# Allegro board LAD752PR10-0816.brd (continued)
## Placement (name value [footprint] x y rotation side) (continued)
PC813  22U_0603_6.3V6M  [C_0603]  228.42 38.39 90 bottom
PC814  1U_0603_6.3V6M  [C_0603]  236.99 36.42 90 bottom
PC815  22U_0603_6.3V6M  [C_0603]  198.25 80.97 0 bottom
PC816  22U_0603_6.3V6M  [C_0603]  196.99 86.24 180 bottom
PC818  330P_0402_50V7K  [C_0402]  122.01 123.41 180 bottom
PC819  22P_0603_50V8  [C_0603]  235.47 41.69 270 bottom
PC820  22U_0603_6.3V6M  [C_0603]  227.34 35.19 180 bottom
PC1000  220U_D7_2VM_R6M  [C_EEFSS0D221R]  165.21 126.27 0 bottom
PC1001  220U 2.5V Y D2 ESR9M H1.9 SX  [C_D2]  170.89 125.35 0 top
PC1002  220U 2.5V Y D2 ESR9M H1.9 SX  [C_D2]  161.7 125.51 180 top
PC1003  47U_0603_6.3V6M  [C_0603]  177.17 127.89 270 bottom
PC1004  47U_0603_6.3V6M  [C_0603]  175.52 127.89 270 bottom
PC1005  47U_0805_6.3V6M  [C_0805]  164.77 107.09 0 top
PC1006  47U_0603_6.3V6M  [C_0603]  178.82 127.89 270 bottom
PC1007  220U 2.5V Y D2 ESR9M H1.9 SX  [C_D2]  151.8 130.46 180 top
PC1008  220U_D7_2VM_R6M  [C_EEFSS0D221R]  151.16 126.27 180 bottom
PC1009  220U 2.5V Y D2 ESR9M H1.9 SX  [C_D2]  151.67 125.7 180 top
PC1010  220U_D7_2VM_R6M  [C_EEFSS0D221R]  155.3 126.27 0 bottom
PC1011  47U_0603_6.3V6M  [C_0603]  151.52 131.79 180 bottom
PC1012  47U_0603_6.3V6M  [C_0603]  145.36 130.59 180 bottom
PC1013  47U_0603_6.3V6M  [C_0603]  151.52 130.59 180 bottom
PC1014  47U_0603_6.3V6M  [C_0603]  145.36 129.32 180 bottom
PC1015  47U_0603_6.3V6M  [C_0603]  151.52 129.32 180 bottom
PC1016  47U_0603_6.3V6M  [C_0603]  145.36 131.86 180 bottom
PC1017  220U_D2_2.5VY_R9M  [C_D2]  180.83 125.38 0 top
PC1018  47U_0805_6.3V6M  [C_0805]  164.77 108.8 0 top
PC1019  10U_0402_6.3V6M  [C_0402]  165.55 113.06 0 top
PC1020  22U_0603_6.3V6M  [C_0603]  156.86 107.66 0 top
PC1021  22U_0603_6.3V6M  [C_0603]  156.86 106.46 0 top
PC1022  22U_0603_6.3V6M  [C_0603]  155.91 107.66 180 top
PC1023  22U_0603_6.3V6M  [C_0603]  155.91 106.46 180 top
PC1024  22U_0603_6.3V6M  [C_0603]  160.61 106.46 180 top
PC1025  22U_0603_6.3V6M  [C_0603]  160.61 107.66 180 top
PC1026  22U_0603_6.3V6M  [C_0603]  161.56 107.66 0 top
PC1027  22U_0603_6.3V6M  [C_0603]  161.56 106.46 0 top
PC1028  22U_0603_6.3V6M  [C_0603]  140.73 108.04 0 top
PC1029  22U_0603_6.3V6M  [C_0603]  138.38 108.04 0 top
PC1030  22U_0603_6.3V6M  [C_0603]  145.43 108.04 0 top
PC1031  22U_0603_6.3V6M  [C_0603]  143.08 108.04 0 top
PC1032  22U_0603_6.3V6M  [C_0603]  147.78 108.04 0 top
PC1033  22U_0603_6.3V6M  [C_0603]  150.51 108.11 0 top
PC1034  22U_0603_6.3V6M  [C_0603]  150.52 109.32 0 top
PC1035  22U_0603_6.3V6M  [C_0603]  150.52 110.66 0 top
PC1036  10U_0402_6.3V6M  [C_0402]  164.68 111.03 180 top
PC1037  10U_0402_6.3V6M  [C_0402]  165.55 112.17 0 top
PC1038  10U_0402_6.3V6M  [C_0402]  165.55 114.46 0 top
PC1039  10U_0402_6.3V6M  [C_0402]  164.68 111.92 180 top
PC1040  10U_0402_6.3V6M  [C_0402]  164.68 110.14 180 top
PC1041  10U_0402_6.3V6M  [C_0402]  165.55 110.14 0 top
PC1042  1U_0201_6.3V6M  [C_0201]  164.84 113.44 180 top
PC1043  1U_0201_6.3V6M  [C_0201]  164.84 114.58 180 top
PC1044  1U_0201_6.3V6M  [C_0201]  164.84 114.01 180 top
PC1045  10U_0402_6.3V6M  [C_0402]  155.48 111.03 180 top
PC1046  10U_0402_6.3V6M  [C_0402]  156.34 109.76 0 top
PC1047  10U_0402_6.3V6M  [C_0402]  155.48 111.92 180 top
PC1048  10U_0402_6.3V6M  [C_0402]  155.48 109.76 180 top
PC1049  10U_0402_6.3V6M  [C_0402]  156.34 111.92 0 top
PC1050  10U_0402_6.3V6M  [C_0402]  158.91 105.19 180 top
PC1051  10U_0402_6.3V6M  [C_0402]  156.34 111.03 0 top
PC1052  10U_0402_6.3V6M  [C_0402]  156.21 105.19 0 top
PC1053  10U_0402_6.3V6M  [C_0402]  158.91 104.3 180 top
PC1054  10U_0402_6.3V6M  [C_0402]  160.09 109.76 0 top
PC1055  10U_0402_6.3V6M  [C_0402]  156.21 104.3 0 top
PC1056  10U_0402_6.3V6M  [C_0402]  159.22 109.76 180 top
PC1057  10U_0402_6.3V6M  [C_0402]  159.22 111.92 180 top
PC1058  10U_0402_6.3V6M  [C_0402]  159.22 111.03 180 top
PC1059  10U_0402_6.3V6M  [C_0402]  153.08 112.72 180 top
PC1060  10U_0402_6.3V6M  [C_0402]  143.12 105.72 0 top
PC1061  10U_0402_6.3V6M  [C_0402]  138.56 104.8 0 top
PC1062  10U_0402_6.3V6M  [C_0402]  140.84 106.6 0 top
PC1063  10U_0402_6.3V6M  [C_0402]  140.85 111.39 0 top
PC1064  10U_0402_6.3V6M  [C_0402]  148.03 109.12 0 top
PC1065  10U_0402_6.3V6M  [C_0402]  145.56 109.11 0 top
PC1066  10U_0402_6.3V6M  [C_0402]  138.6 110.48 0 top
PC1067  10U_0402_6.3V6M  [C_0402]  143.14 111.39 0 top
PC1068  10U_0402_6.3V6M  [C_0402]  138.56 105.7 0 top
PC1069  10U_0402_6.3V6M  [C_0402]  143.12 104.81 0 top
PC1070  10U_0402_6.3V6M  [C_0402]  140.86 110.52 0 top
PC1071  10U_0402_6.3V6M  [C_0402]  160.09 111.92 0 top
PC1072  10U_0402_6.3V6M  [C_0402]  159.77 104.3 0 top
PC1073  10U_0402_6.3V6M  [C_0402]  160.09 111.03 0 top
PC1074  10U_0402_6.3V6M  [C_0402]  159.77 105.19 0 top
PC1075  10U_0402_6.3V6M  [C_0402]  162.78 111.92 180 top
PC1076  10U_0402_6.3V6M  [C_0402]  162.78 109.76 180 top
PC1077  10U_0402_6.3V6M  [C_0402]  162.46 104.3 180 top
PC1078  10U_0402_6.3V6M  [C_0402]  162.78 111.03 180 top
PC1079  10U_0402_6.3V6M  [C_0402]  163.33 104.3 0 top
PC1080  10U_0402_6.3V6M  [C_0402]  163.33 105.19 0 top
PC1081  10U_0402_6.3V6M  [C_0402]  166.02 105.19 180 top
PC1082  10U_0402_6.3V6M  [C_0402]  162.46 105.19 180 top
PC1083  10U_0402_6.3V6M  [C_0402]  155.35 105.19 180 top
PC1084  10U_0402_6.3V6M  [C_0402]  155.35 104.3 180 top
PC1085  10U_0402_6.3V6M  [C_0402]  147.78 104.79 0 top
PC1086  10U_0402_6.3V6M  [C_0402]  147.79 106.59 0 top
PC1087  10U_0402_6.3V6M  [C_0402]  145.45 104.79 0 top
PC1088  10U_0402_6.3V6M  [C_0402]  147.97 111.44 0 top
PC1089  10U_0402_6.3V6M  [C_0402]  145.44 106.59 0 top
PC1090  10U_0402_6.3V6M  [C_0402]  150.05 104.8 0 top
PC1091  10U_0402_6.3V6M  [C_0402]  153.05 111.85 180 top
PC1092  10U_0402_6.3V6M  [C_0402]  145.44 105.69 0 top
PC1093  10U_0402_6.3V6M  [C_0402]  150.06 105.68 0 top
PC1094  10U_0402_6.3V6M  [C_0402]  140.83 104.81 0 top
PC1095  10U_0402_6.3V6M  [C_0402]  145.49 111.4 0 top
PC1096  10U_0402_6.3V6M  [C_0402]  143.14 110.52 0 top
PC1097  1U_0201_6.3V6M  [C_0201]  163.12 101.12 180 top
PC1098  1U_0201_6.3V6M  [C_0201]  164.65 102.58 180 top
PC1099  1U_0201_6.3V6M  [C_0201]  158.66 101.7 0 top
PC1100  1U_0201_6.3V6M  [C_0201]  159.82 109 180 top
PC1101  1U_0201_6.3V6M  [C_0201]  165.27 102.58 0 top
PC1102  1U_0201_6.3V6M  [C_0201]  162.6 113.25 0 top
PC1103  1U_0201_6.3V6M  [C_0201]  162.6 112.68 0 top
PC1104  1U_0201_6.3V6M  [C_0201]  161.98 113.25 180 top
PC1105  1U_0201_6.3V6M  [C_0201]  162.23 109 180 top
PC1106  1U_0201_6.3V6M  [C_0201]  161.98 112.68 180 top
PC1107  1U_0201_6.3V6M  [C_0201]  161.98 114.27 180 top
PC1108  1U_0201_6.3V6M  [C_0201]  161.98 114.84 180 top
PC1109  1U_0201_6.3V6M  [C_0201]  162.6 114.84 0 top
PC1110  1U_0201_6.3V6M  [C_0201]  162.6 114.27 0 top
PC1111  1U_0201_6.3V6M  [C_0201]  160.44 109 0 top
PC1112  10U_0402_6.3V6M  [C_0402]  145.51 110.52 0 top
PC1113  10U_0402_6.3V6M  [C_0402]  150.08 106.58 0 top
PC1114  10U_0402_6.3V6M  [C_0402]  138.56 106.6 0 top
PC1115  10U_0402_6.3V6M  [C_0402]  140.88 109.12 0 top
PC1116  10U_0402_6.3V6M  [C_0402]  140.84 105.7 0 top
PC1117  10U_0402_6.3V6M  [C_0402]  138.6 111.37 0 top
PC1118  10U_0402_6.3V6M  [C_0402]  138.58 109.13 0 top
PC1119  10U_0402_6.3V6M  [C_0402]  147.98 110.53 0 top
PC1120  10U_0402_6.3V6M  [C_0402]  143.12 106.62 0 top
PC1121  10U_0402_6.3V6M  [C_0402]  147.79 105.69 0 top
PC1122  10U_0402_6.3V6M  [C_0402]  143.12 109.11 0 top
PC1123  1U_0201_6.3V6M  [C_0201]  155.36 113.25 0 top
PC1124  1U_0201_6.3V6M  [C_0201]  157.15 112.68 180 top
PC1125  1U_0201_6.3V6M  [C_0201]  155.36 112.68 0 top
PC1126  1U_0201_6.3V6M  [C_0201]  154.74 113.25 180 top
PC1127  1U_0201_6.3V6M  [C_0201]  157.15 113.25 180 top
PC1128  1U_0201_6.3V6M  [C_0201]  157.15 114.84 180 top
PC1129  1U_0201_6.3V6M  [C_0201]  154.74 112.68 180 top
PC1130  1U_0201_6.3V6M  [C_0201]  157.15 114.27 180 top
PC1131  1U_0201_6.3V6M  [C_0201]  155.36 114.84 0 top
PC1132  1U_0201_6.3V6M  [C_0201]  155.36 114.27 0 top
PC1133  1U_0201_6.3V6M  [C_0201]  154.74 114.27 180 top
PC1134  1U_0201_6.3V6M  [C_0201]  163.74 101.12 0 top
PC1135  1U_0201_6.3V6M  [C_0201]  154.74 114.84 180 top
PC1136  1U_0201_6.3V6M  [C_0201]  162.86 109 0 top
PC1137  1U_0201_6.3V6M  [C_0201]  160.44 103.15 0 top
PC1138  1U_0201_6.3V6M  [C_0201]  152.57 113.9 180 top
PC1139  1U_0201_6.3V6M  [C_0201]  145.87 114.44 0 top
PC1140  1U_0201_6.3V6M  [C_0201]  144.03 103.5 180 top
PC1141  1U_0201_6.3V6M  [C_0201]  150.13 113.89 180 top
PC1142  1U_0201_6.3V6M  [C_0201]  150.18 112.26 180 top
PC1143  1U_0201_6.3V6M  [C_0201]  146.68 103.51 180 top
PC1144  1U_0201_6.3V6M  [C_0201]  149.09 102.94 180 top
PC1145  1U_0201_6.3V6M  [C_0201]  138.49 112.78 0 top
PC1146  1U_0201_6.3V6M  [C_0201]  149.09 103.51 180 top
PC1147  1U_0201_6.3V6M  [C_0201]  144.03 102.92 180 top
PC1148  1U_0201_6.3V6M  [C_0201]  149.71 102.94 0 top
PC1149  1U_0201_6.3V6M  [C_0201]  140.31 112.19 180 top
PC1150  1U_0201_6.3V6M  [C_0201]  150.18 112.85 180 top
PC1151  1U_0201_6.3V6M  [C_0201]  140.96 112.78 0 top
PC1152  1U_0201_6.3V6M  [C_0201]  148.38 112.26 0 top
PC1153  1U_0201_6.3V6M  [C_0201]  142.79 112.19 180 top
PC1154  1U_0201_6.3V6M  [C_0201]  148.38 112.84 0 top
PC1155  1U_0201_6.3V6M  [C_0201]  143.45 112.79 0 top
PC1156  1U_0201_6.3V6M  [C_0201]  149.71 103.51 0 top
PC1157  1U_0201_6.3V6M  [C_0201]  148.33 113.88 0 top
PC1158  1U_0201_6.3V6M  [C_0201]  150.81 112.28 0 top
PC1159  1U_0201_6.3V6M  [C_0201]  148.33 114.46 0 top
PC1160  1U_0201_6.3V6M  [C_0201]  152.57 114.47 180 top
PC1161  1U_0201_6.3V6M  [C_0201]  158.02 102.58 0 top
PC1162  1U_0201_6.3V6M  [C_0201]  162.8 101.76 180 top
PC1163  1U_0201_6.3V6M  [C_0201]  162.23 103.15 180 top
PC1164  1U_0201_6.3V6M  [C_0201]  162.86 103.15 0 top
PC1165  1U_0201_6.3V6M  [C_0201]  158.02 103.16 0 top
PC1166  1U_0201_6.3V6M  [C_0201]  158.03 109 0 top
PC1167  1U_0201_6.3V6M  [C_0201]  159.82 103.15 180 top
PC1168  1U_0201_6.3V6M  [C_0201]  159.57 112.68 180 top
PC1169  1U_0201_6.3V6M  [C_0201]  157.41 109 180 top
PC1170  1U_0201_6.3V6M  [C_0201]  160.19 113.25 0 top
PC1171  1U_0201_6.3V6M  [C_0201]  159.57 113.25 180 top
PC1172  1U_0201_6.3V6M  [C_0201]  160.19 112.68 0 top
PC1173  1U_0201_6.3V6M  [C_0201]  157.78 112.68 0 top
PC1174  1U_0201_6.3V6M  [C_0201]  157.78 113.25 0 top
PC1175  1U_0201_6.3V6M  [C_0201]  159.57 114.27 180 top
PC1176  1U_0201_6.3V6M  [C_0201]  144.88 103.51 0 top
PC1177  1U_0201_6.3V6M  [C_0201]  145.9 112.23 0 top
PC1178  1U_0201_6.3V6M  [C_0201]  144.88 102.94 0 top
PC1179  1U_0201_6.3V6M  [C_0201]  145.87 113.86 0 top
PC1180  1U_0201_6.3V6M  [C_0201]  142.77 113.84 180 top
PC1181  1U_0201_6.3V6M  [C_0201]  147.3 103.51 0 top
PC1182  1U_0201_6.3V6M  [C_0201]  146.68 102.94 180 top
PC1183  1U_0201_6.3V6M  [C_0201]  145.23 114.43 180 top
PC1184  1U_0201_6.3V6M  [C_0201]  145.27 112.8 180 top
PC1185  1U_0201_6.3V6M  [C_0201]  145.23 113.85 180 top
PC1186  1U_0201_6.3V6M  [C_0201]  139.82 102.92 0 top
PC1187  1U_0201_6.3V6M  [C_0201]  138.48 112.19 0 top
PC1188  1U_0201_6.3V6M  [C_0201]  140.31 112.77 180 top
PC1189  1U_0201_6.3V6M  [C_0201]  139.2 103.49 180 top
PC1190  1U_0201_6.3V6M  [C_0201]  140.3 114.42 180 top
PC1191  1U_0201_6.3V6M  [C_0201]  139.2 102.92 180 top
PC1192  1U_0201_6.3V6M  [C_0201]  140.3 113.84 180 top
PC1193  1U_0201_6.3V6M  [C_0201]  145.27 112.21 180 top
PC1194  1U_0201_6.3V6M  [C_0201]  150.13 114.47 180 top
PC1195  1U_0201_6.3V6M  [C_0201]  143.42 113.86 0 top
PC1196  1U_0201_6.3V6M  [C_0201]  140.96 112.19 0 top
PC1197  1U_0201_6.3V6M  [C_0201]  143.41 114.43 0 top
PC1198  1U_0201_6.3V6M  [C_0201]  147.3 102.94 0 top
PC1199  1U_0201_6.3V6M  [C_0201]  159.57 114.84 180 top
PC1200  1U_0201_6.3V6M  [C_0201]  157.78 114.27 0 top
PC1201  1U_0201_6.3V6M  [C_0201]  157.78 114.84 0 top
PC1202  1U_0201_6.3V6M  [C_0201]  160.19 114.27 0 top
PC1203  1U_0201_6.3V6M  [C_0201]  160.19 114.84 0 top
PC1204  1U_0201_6.3V6M  [C_0201]  165.27 103.15 0 top
PC1205  1U_0201_6.3V6M  [C_0201]  164.65 103.15 180 top
PC1206  1U_0201_6.3V6M  [C_0201]  154.99 102.58 180 top
PC1207  1U_0201_6.3V6M  [C_0201]  165.07 102.01 0 top
PC1208  1U_0201_6.3V6M  [C_0201]  154.99 103.15 180 top
PC1209  1U_0201_6.3V6M  [C_0201]  155.62 103.15 0 top
PC1210  1U_0201_6.3V6M  [C_0201]  155.44 101.76 180 top
PC1211  1U_0201_6.3V6M  [C_0201]  155.62 102.58 0 top
PC1212  1U_0201_6.3V6M  [C_0201]  157.41 102.58 180 top
PC1213  1U_0201_6.3V6M  [C_0201]  157.85 101.12 180 top
PC1214  1U_0201_6.3V6M  [C_0201]  145.9 112.81 0 top
PC1215  1U_0201_6.3V6M  [C_0201]  142.79 112.78 180 top
PC1216  1U_0201_6.3V6M  [C_0201]  150.81 112.87 0 top
PC1217  1U_0201_6.3V6M  [C_0201]  147.69 114.45 180 top
PC1218  1U_0201_6.3V6M  [C_0201]  150.77 113.89 0 top
PC1219  1U_0201_6.3V6M  [C_0201]  140.95 114.42 0 top
PC1220  1U_0201_6.3V6M  [C_0201]  151.5 102.94 180 top
PC1221  1U_0201_6.3V6M  [C_0201]  143.44 112.2 0 top
PC1222  1U_0201_6.3V6M  [C_0201]  142.77 114.42 180 top
PC1223  1U_0201_6.3V6M  [C_0201]  142.24 103.49 0 top
PC1224  1U_0201_6.3V6M  [C_0201]  140.95 113.83 0 top
PC1225  1U_0201_6.3V6M  [C_0201]  138.48 113.84 0 top
PC1226  1U_0201_6.3V6M  [C_0201]  138.47 114.43 0 top
PC1227  1U_0201_6.3V6M  [C_0201]  139.82 103.49 0 top
PC1228  1U_0201_6.3V6M  [C_0201]  150.77 114.46 0 top
PC1229  1U_0201_6.3V6M  [C_0201]  141.62 102.93 180 top
PC1230  1U_0201_6.3V6M  [C_0201]  147.74 112.25 180 top
PC1231  1U_0201_6.3V6M  [C_0201]  142.25 102.91 0 top
PC1232  1U_0201_6.3V6M  [C_0201]  147.69 113.86 180 top
PC1233  1U_0201_6.3V6M  [C_0201]  151.5 103.51 180 top
PC1234  1U_0201_6.3V6M  [C_0201]  147.74 112.83 180 top
PC1235  1U_0201_6.3V6M  [C_0201]  141.62 103.5 180 top
PC1236  1U_0201_6.3V6M  [C_0201]  155.62 109 0 top
PC1237  1U_0201_6.3V6M  [C_0201]  157.41 103.15 180 top
PC1238  1U_0201_6.3V6M  [C_0201]  154.99 109 180 top
PC1300  22U_0603_6.3V6M  [C_0603]  101.71 51.96 0 bottom
PC1301  0.1U_0402_16V7K  [C_0402]  100.12 50.71 90 bottom
PC1302  22U_0603_6.3V6M  [C_0603]  201.94 76.11 90 bottom
PC1303  22U_0603_6.3V6M  [C_0603]  100.91 38.51 180 bottom
PC1304  22U_0603_6.3V6M  [C_0603]  100.91 39.78 180 bottom
PC1305  22P_0603_50V8  [C_0603]  100.91 41.05 180 bottom
PC1306  22U_0603_6.3V6M  [C_0603]  101.71 50.75 0 bottom
PC1307  1U_0603_6.3V6M  [C_0603]  104.18 49.63 270 bottom
PC1308  22U_0603_6.3V6M  [C_0603]  200.73 76.11 90 bottom
PC1309  10U_0603_6.3V6M  [C_0603]  214.13 75.91 270 bottom
PC1310  22P_0603_50V8  [C_0603]  211.65 75.91 270 bottom
PC1311  0.01U_0402_16V7K  [C_0402]  202.02 72.23 180 top
PC1312  1U_0603_6.3V6M  [C_0603]  202.89 79.34 180 bottom
PC1313  10U_0603_6.3V6M  [C_0603]  212.86 75.91 270 bottom
PC1314  22U_0603_6.3V6M  [C_0603]  210.32 80.3 180 bottom
PC1315  22U_0603_6.3V6M  [C_0603]  210.32 79.04 180 bottom
PC5002  4.7U_0402_6.3V6M  [C_0402]  182.1 141.73 180 top
PC5003  1U_0603_6.3V6M  [C_0603]  124.21 113.76 0 bottom
PC5005  1U_0402_6.3V6K  [C_0402]  157.33 141.51 270 top
PC5006  1U_0402_6.3V6K  [C_0402]  165.88 139.99 0 top
PC5007  1U_0402_6.3V6K  [C_0402]  174.03 141.54 270 top
PC5008  1U_0402_6.3V6K  [C_0402]  141.33 144.79 270 top
PC5009  1U_0402_6.3V6K  [C_0402]  149.63 144.85 270 top
PC5010  1000P_0402_50V7K  [C_0402]  119.56 134.34 0 bottom
PC5011  1000P_0402_50V7K  [C_0402]  121.1 147.36 270 bottom
PC5013  1U_0402_25V6K  [C_0402]  163.2 142.77 0 top
PC5014  1000P_0402_50V7K  [C_0402]  163.2 141 0 top
PC5015  1U_0402_25V6K  [C_0402]  171.65 142.65 270 top
PC5016  1000P_0402_50V7K  [C_0402]  172.35 145.13 90 top
PC5017  1U_0402_25V6K  [C_0402]  184.98 145.83 270 top
PC5018  1000P_0402_50V7K  [C_0402]  184.1 145.83 270 top
PC5019  1U_0402_25V6K  [C_0402]  147.14 146.15 270 top
PC5020  1000P_0402_50V7K  [C_0402]  148.03 148.5 90 top
PC5021  1U_0402_25V6K  [C_0402]  157.16 148.8 180 top
PC5022  1000P_0402_50V7K  [C_0402]  155.65 146.09 270 top
PC5023  1U_0402_25V6K  [C_0402]  184.91 142.3 180 top
PC5024  1000P_0402_50V7K  [C_0402]  186.06 139.1 270 top
PC5025  1U_0402_25V6K  [C_0402]  118.7 118.84 180 bottom
PC5026  1000P_0402_50V7K  [C_0402]  118.7 119.79 180 bottom
PC5027  2.2U_0402_16V6K  [C_0402]  123.07 113.77 270 bottom
PC6000  4.7U_0603_6.3V  [C_0603]  287.79 55.47 180 top
PC6001  0.01U_0603_25V7K  [C_0603]  293.76 49.44 180 top
PC6002  0.1U_0603_16V  [C_0603]  286.43 57.59 0 top
PC6003  0.1U_0402_16V7K  [C_0402]  286.99 56.55 0 top
PC6004  0.01U_0402_16V  [C_0402]  283.42 57.5 180 top
PC6005  0.068U_0402_16V7K  [C_0402]  281.44 54.12 90 bottom
PC6006  0.068U_0402_16V7K  [C_0402]  280.55 59.77 90 bottom
PC6007  330P_0402_25V  [C_0402]  289.11 63.6 0 bottom
PC6008  2200P_0402_25V  [C_0402]  288.17 62.66 270 bottom
PC6009  47P_0402_50V8J  [C_0402]  289.96 61.75 180 bottom
PC6010  0.068U_0402_16V7K  [C_0402]  281.68 63.46 180 bottom
PC6011  1000P_0402_25V  [C_0402]  292.69 61.75 180 bottom
PC6012  2200P_0603_50V7K  [C_0603]  291.98 64.1 270 bottom
PC6013  2200P_0603_50V7K  [C_0603]  293.25 65.06 270 bottom
PC6014  1500P_0402_50V7K  [C_0402]  285.33 61.69 180 bottom
PC6015  390P_0402_50V7K  [C_0402]  285.33 62.64 180 bottom
PC6016  1000P_0402_25V  [C_0402]  286.58 59.52 90 top
PC6017  2200P_0402_25V  [C_0402]  287.16 65.39 270 bottom
PC6018  1000P_0402_25V  [C_0402]  283.98 59.96 90 top
PC6019  330P_0402_25V  [C_0402]  288.35 50.13 0 bottom
PC6020  2200P_0402_25V  [C_0402]  287.35 51.14 90 bottom
PC6021  47P_0402_50V8J  [C_0402]  290.13 51.02 0 bottom
PC6022  0.068U_0402_16V7K  [C_0402]  283.93 52.36 180 bottom
PC6023  1000P_0402_25V  [C_0402]  283.03 50.57 90 bottom
PC6024  1000P_0402_25V  [C_0402]  286.7 53.5 0 top
PC6025  1500P_0402_50V7K  [C_0402]  286.46 49.38 270 bottom
PC6026  390P_0402_50V7K  [C_0402]  287.35 49.38 270 bottom
PC6027  1000P_0402_25V  [C_0402]  284.91 54.46 270 top
PC6028  2200P_0402_25V  [C_0402]  286.46 51.23 270 bottom
PC6029  0.068U_0402_16V7K  [C_0402]  281.44 58.01 90 bottom
PC6107  1U_0402_25V6K  [C_0402]  250.83 51.49 270 bottom
PC6108  1000P_0402_50V7K  [C_0402]  254.25 52.32 90 top
PC6109  0.1U_0402_25V6  [C_0402]  252.48 52.34 90 top
PC6110  2200P_0402_50V7K  [C_0402]  253.36 52.34 90 top
PC6111  10U_0805_25V6K~D  [C_0805]  254.7 51.36 270 bottom
PC6112  10U_0805_25V6K~D  [C_0805]  254.73 51.34 270 top
PC6113  10U_0805_25V6K~D  [C_0805]  252.94 51.36 270 bottom
PC6114  10U_0805_25V6K~D  [C_0805]  253 51.34 270 top
PC6117  1U_0603_25V6K  [C_0603]  249.42 55.24 90 top
PC6118  2.2U_0603_10V6K  [C_0603]  247.91 54.12 0 top
PC6127  0.22U_0603_25V7K  [C_0603]  249.75 50.06 90 bottom
PC6128  2200P_0402_50V7K  [C_0402]  252.82 59.55 0 top
PC6129  100U_25V_M  [C_ECST250ADA101MF611]  266.26 38.73 270 bottom
PC6131  100U_25V_M  [C_ECST250ADA101MF611]  261.28 37.05 0 bottom
PC6205  1U_0603_25V6K  [C_0603]  240.9 55.2 90 top
PC6206  2.2U_0603_10V6K  [C_0603]  239.32 54.03 0 top
PC6207  1U_0402_25V6K  [C_0402]  242.3 51.53 270 bottom
PC6208  1000P_0402_50V7K  [C_0402]  242.41 51.51 270 top
PC6209  0.1U_0402_25V6  [C_0402]  240.56 51.51 270 top
PC6210  2200P_0402_50V7K  [C_0402]  241.47 51.51 270 top
PC6211  10U_0805_25V6K~D  [C_0805]  245.49 51.36 270 top
PC6212  10U_0805_25V6K~D  [C_0805]  245.42 51.43 270 bottom
PC6213  10U_0805_25V6K~D  [C_0805]  243.76 51.36 270 top
PC6214  10U_0805_25V6K~D  [C_0805]  243.66 51.43 270 bottom
PC6215  0.22U_0603_25V7K  [C_0603]  241.18 50.07 90 bottom
PC6216  2200P_0402_50V7K  [C_0402]  244.27 59.46 0 top
PC6217  1U_0603_25V6K  [C_0603]  232.3 55.2 90 top
PC6218  2.2U_0603_10V6K  [C_0603]  230.76 53.94 0 top
PC6219  1U_0402_25V6K  [C_0402]  233.73 51.53 270 bottom
PC6220  1000P_0402_50V7K  [C_0402]  233.83 51.51 270 top
PC6221  0.1U_0402_25V6  [C_0402]  231.99 51.51 270 top
PC6222  2200P_0402_50V7K  [C_0402]  232.9 51.51 270 top
PC6223  10U_0805_25V6K~D  [C_0805]  235.19 51.36 270 top
PC6224  10U_0805_25V6K~D  [C_0805]  236.91 51.36 270 top
PC6225  10U_0805_25V6K~D  [C_0805]  236.85 51.43 270 bottom
PC6226  10U_0805_25V6K~D  [C_0805]  235.09 51.43 270 bottom
PC6227  0.22U_0603_25V7K  [C_0603]  232.61 50.07 90 bottom
PC6228  2200P_0402_50V7K  [C_0402]  235.71 59.46 0 top
PC6305  1U_0603_25V6K  [C_0603]  223.62 56.22 90 top
PC6306  2.2U_0603_10V6K  [C_0603]  222.06 54.96 0 top
PC6307  1U_0402_25V6K  [C_0402]  225.04 52.53 270 bottom
PC6308  1000P_0402_50V7K  [C_0402]  225.14 52.51 270 top
PC6309  0.1U_0402_25V6  [C_0402]  223.29 52.51 270 top
PC6310  2200P_0402_50V7K  [C_0402]  224.21 52.51 270 top
PC6311  10U_0805_25V6K~D  [C_0805]  228.16 50.9 270 bottom
PC6312  10U_0805_25V6K~D  [C_0805]  226.39 50.9 270 bottom
PC6313  10U_0805_25V6K~D  [C_0805]  226.49 52.43 270 top
PC6314  10U_0805_25V6K~D  [C_0805]  228.22 52.43 270 top
PC6315  0.22U_0603_25V7K  [C_0603]  223.92 51.07 90 bottom
PC6316  2200P_0402_50V7K  [C_0402]  227.03 60.46 0 top
PC6400  1U_0603_25V6K  [C_0603]  263.15 57.82 90 top
PC6401  2.2U_0603_10V6K  [C_0603]  266.01 53.75 180 bottom
PC6402  1U_0402_25V6K  [C_0402]  276.55 50.39 270 bottom
PC6403  1000P_0402_50V7K  [C_0402]  277.44 50.39 270 bottom
PC6404  0.1U_0402_25V6  [C_0402]  277.44 51.33 90 bottom
PC6405  2200P_0402_50V7K  [C_0402]  275.68 50.39 270 bottom
PC6406  10U_0805_25V6K~D  [C_0805]  274.38 50.36 270 bottom
PC6407  10U_0805_25V6K~D  [C_0805]  275.97 51.56 90 bottom
PC6408  10U_0805_25V6K~D  [C_0805]  272.63 50.41 270 bottom
PC6409  10U_0805_25V6K~D  [C_0805]  270.86 50.41 270 bottom
PC6410  0.22U_0603_25V7K  [C_0603]  269.35 48.88 90 bottom
PC6411  2200P_0402_50V7K  [C_0402]  275.52 57.44 0 bottom
PC6501  22U_0805_6.3VAM  [C_0805]  268.84 68.29 90 bottom
PC6502  22U_0805_6.3VAM  [C_0805]  271.18 68.22 90 bottom
PC6503  22U_0805_6.3VAM  [C_0805]  273.64 68.22 90 bottom
PC6504  22U_0805_6.3VAM  [C_0805]  275.43 68.24 90 bottom
PC6505  22U_0603_6.3V6M  [C_0603]  255.7 79.09 180 top
PC6506  22U_0603_6.3V6M  [C_0603]  252.76 77.1 90 top
PC6507  22U_0603_6.3V6M  [C_0603]  250.45 77.18 90 top
PC6508  470U_D2_2VM_R4.5M  [C_D2]  266.38 65.59 270 bottom
PC6509  470U_D2_2VM_R4.5M  [C_D2]  271.66 78.62 90 top
PC6510  22U_0805_6.3VAM  [C_0805]  236.34 100.29 90 top
PC6511  22U_0805_6.3VAM  [C_0805]  238.38 99.98 0 top
PC6512  22U_0805_6.3VAM  [C_0805]  234.27 96.12 180 top
PC6513  22U_0805_6.3VAM  [C_0805]  236.33 95.86 270 top
PC6514  22U_0805_6.3VAM  [C_0805]  242.34 96.27 90 top
PC6515  22U_0805_6.3VAM  [C_0805]  238.38 93.9 0 top
PC6516  22U_0805_6.3VAM  [C_0805]  238.38 95.98 0 top
PC6517  22U_0805_6.3VAM  [C_0805]  238.38 98 0 top
PC6518  22U_0805_6.3VAM  [C_0805]  236.62 97.97 180 top
PC6519  22U_0805_6.3VAM  [C_0805]  230.73 65.44 270 top
PC6520  22U_0805_6.3VAM  [C_0805]  235.99 65.32 270 top
PC6521  22U_0805_6.3VAM  [C_0805]  237.82 65.32 270 top
PC6522  22U_0805_6.3VAM  [C_0805]  239.65 65.38 270 top
PC6523  22U_0805_6.3VAM  [C_0805]  246.43 65.32 270 top
PC6524  22U_0805_6.3VAM  [C_0805]  248.26 65.32 270 top
PC6525  22U_0805_6.3VAM  [C_0805]  231.65 98.09 0 top
PC6526  22U_0805_6.3VAM  [C_0805]  230.07 94.18 90 top
PC6527  22U_0805_6.3VAM  [C_0805]  232.75 100.08 0 top
PC6528  22U_0805_6.3VAM  [C_0805]  244.59 65.38 270 top
PC6529  22U_0805_6.3VAM  [C_0805]  227.11 65.44 270 top
PC6530  22U_0805_6.3VAM  [C_0805]  228.94 65.44 270 top
PC6531  22U_0805_6.3VAM  [C_0805]  233.18 74.07 0 bottom
PC6532  22U_0805_6.3VAM  [C_0805]  260.75 62.76 270 bottom
PC6533  22U_0805_6.3VAM  [C_0805]  259.19 73.56 90 bottom
PC6534  22U_0805_6.3VAM  [C_0805]  242.34 103.92 270 top
PC6535  22U_0805_6.3VAM  [C_0805]  234.38 92.08 180 top
PC6536  22U_0805_6.3VAM  [C_0805]  238.39 104.12 0 top
PC6537  22U_0805_6.3VAM  [C_0805]  257.31 73.54 90 bottom
PC6538  22U_0805_6.3VAM  [C_0805]  255.47 73.54 90 bottom
PC6539  22U_0805_6.3VAM  [C_0805]  253.63 73.54 90 bottom
PC6540  22U_0805_6.3VAM  [C_0805]  237.85 74.07 0 bottom
PC6541  22U_0805_6.3VAM  [C_0805]  241.79 74.07 0 bottom
PC6542  470U_D2_2VM_R4.5M  [C_D2]  221.54 80.17 0 top
PC6543  470U_D2_2VM_R4.5M  [C_D2]  257.31 66.11 270 bottom
PC6544  470U_D2_2VM_R4.5M  [C_D2]  262.57 69.97 90 bottom
PC6545  470U_D2_2VM_R4.5M  [C_D2]  258.11 70.49 180 bottom
PC6546  470U_D2_2VM_R4.5M  [C_D2]  247.95 70.53 180 bottom
PC6547  470U_D2_2VM_R4.5M  [C_D2]  237.98 70.58 180 bottom
PC6548  470U_D2_2VM_R4.5M  [C_D2]  228.01 71.51 180 bottom
PC6549  470U_D2_2VM_R4.5M  [C_D2]  218.5 65.91 270 bottom
PC8200  2.2U_0603_16V6K  [C_0603]  273.88 157.51 180 bottom
PC8201  2200P_0402_50V7K  [C_0402]  274.9 164.55 90 top
PC8202  0.1U_0402_25V6  [C_0402]  274.01 164.55 90 bottom
PC8203  10U_0805_25V6K~D  [C_0805]  272.68 164.73 90 top
PC8204  10U_0805_25V6K~D  [C_0805]  272.68 164.73 90 bottom
PC8205  0.1U_0402_25V6  [C_0402]  282 160.69 180 top
PC8206  0.22U_0603_25V7K  [C_0603]  274.65 155.8 180 top
PC8207  220U_D2 SX_2VY_R9M  [C_D2]  262.01 153.19 180 bottom
PC8208  220U_D2 SX_2VY_R9M  [C_D2]  258.83 157.61 90 bottom
PC8210  680P_0402_50V7K  [C_0402]  271.53 157.97 270 bottom
PC8211  0.1U_0402_25V6  [C_0402]  277.83 154.64 0 top
PC8212  10U_0805_25V6K~D  [C_0805]  270.24 164.24 180 top
PC8213  0.22U_0603_25V7K  [C_0603]  275.34 160.81 90 bottom
PC8214  10U_0805_25V6K~D  [C_0805]  270.24 162.53 180 top
PC8215  0.1U_0402_25V6  [C_0402]  281.09 158.91 0 top
PC8216  47P_0402_50V8J  [C_0402]  279.03 160.48 90 top
PC8217  0.033U_0402_16V7K  [C_0402]  281.07 156.85 0 top
PC8218  0.1U_0402_25V6  [C_0402]  278.14 162.27 0 top
PC8219  680P_0402_50V7K  [C_0402]  264.68 172.13 270 top
PC8220  1000P_0402_50V7K  [C_0402]  274.9 164.55 90 bottom
PC8221  1U_0402_25V6K  [C_0402]  274.01 164.55 90 top
PC8222  0.1U_0402_25V6  [C_0402]  280.91 150.5 0 top
PC8226  22U_0805_6.3VAM  [C_0805]  266.38 68.35 90 bottom
PD1  SM24_SOT23  [TP0610K-T1-E3_SOT23-3]  267.03 33.26 0 top
PD2  -  [TVNST52302AB0_SOT523-3]  83.4 13.08 180 top
PD3  -  [TVNST52302AB0_SOT523-3]  79.22 7.59 180 top
PD5  -  [BAS40CW_SOT323-3]  284.32 32.91 270 bottom
PD100  -  [BAS40CW_SOT323-3]  60.51 45.24 90 top
PD101  -  [LL4148_LL34-2]  53.38 17.37 0 bottom
PD700  BAT54CW-7-F SOT-323  [BAT54CW_SOT323-3]  60.27 19.02 90 bottom
PH1  100K_0402_1%_B25/50 4250K  [R_0402]  153.29 110.42 270 top
PH500  470K_0402_5%_B25/50 4700K  [R_0402]  139.68 148.13 90 bottom
PH501  10K +-5% 0402 B25/50 4250K  [R_0402]  187.13 133.2 180 bottom
PH502  10K +-5% 0402 B25/50 4250K  [R_0402]  123.7 147.81 180 top
PH503  10K +-5% 0402 B25/50 4250K  [R_0402]  163.38 129.13 0 bottom
PH504  470K_0402_5%_B25/50 4700K  [R_0402]  163.06 146.78 0 bottom
PH6000  100K_0402_1%_TSM0B104F4251RZ  [R_0402]  246.5 61.8 90 bottom
PH6001  100K_0402_1%_TSM0B104F4251RZ  [R_0402]  277 60.12 270 bottom
PJP100  -  [JUMP_43X118]  44.99 43.63 90 top
PJP101  -  [JUMP_43X118]  38.49 42.96 90 top
PJP102  -  [JUMP_43X118]  46.11 20.18 90 top
PJP104  -  [JUMP_43X118]  40.9 20.18 90 top
PJP200  -  [JUMP_43X118]  97.23 30.26 0 top
PJP201  -  [JUMP_43X118]  97.23 24.92 0 top
PJP202  -  [JUMP_43X39]  93.1 50.07 90 bottom
PJP203  -  [JUMP_43X39]  89.09 31.53 90 top
PJP300  -  [JUMP_43X118]  242.17 36.18 90 bottom
PJP301  -  [JUMP_43X39]  258.31 25.43 0 top
PJP302  -  [JUMP_43X118]  247.47 36.19 90 bottom
PJP504  -  [JUMP_43X39]  118.37 121.84 270 bottom
PJP505  -  [JUMP_43X118]  122.69 102.69 270 bottom
PJP800  -  [JUMP_43X39]  199.34 71.27 90 bottom
PJP801  -  [JUMP_43X79]  198.82 84.87 0 bottom
PJP802  -  [JUMP_43X39]  240.56 39.85 180 bottom
PJP803  -  [JUMP_43X79]  226.71 37.69 180 bottom
PJP1300  -  [JUMP_43X79]  102.78 40.61 0 bottom
PJP1301  -  [JUMP_43X79]  101.62 54.96 270 bottom
PJP1302  -  [JUMP_43X79]  212.44 78.39 0 bottom
PJP1303  -  [JUMP_43X79]  202.45 70.67 90 bottom
PJP8200  -  [JUMP_43X39]  273.68 162.97 0 top
PJP8201  -  [JUMP_43X118]  256.6 149.53 270 bottom
PJP8202  -  [JUMP_43X118]  261.91 149.52 270 bottom
PJPDC1  ACES_50290-01301-P01  [ACES_50290-01301-P01_13P-T]  66.32 43.56 0 bottom
PL1  SMB3025500YA_2P  [CHENG_SMB3025500YA_2P]  81.86 33.75 180 bottom
PL2  BLM15HG601SN1D_2P  [MURAT_BLM15HG601SN1D_2P]  29.09 40.49 90 bottom
PL3  SMB3025500YA_2P  [CHENG_SMB3025500YA_2P]  81.86 37.27 180 bottom
PL4  SMB3025500YA_2P  [CHENG_SMB3025500YA_2P]  83.38 24.42 270 bottom
PL5  SMB3025500YA_2P  [CHENG_SMB3025500YA_2P]  87.13 24.42 270 bottom
PL100  1UH_6.6A_20%_5X5X3_M  [L_5X5X3_M_2P]  53.41 33.05 90 bottom
PL101  2.2UH_PCMB104T-2R2MS_12A_20%  [CYNTE_PCMB104T-2R2MS_2P]  49.54 19.12 90 bottom
PL102  2.2UH_PCMB104T-2R2MS_12A_20%  [CYNTE_PCMB104T-2R2MS_2P]  45.22 33.91 90 bottom
PL201  1UH_11A_20%_7X7X3_M  [L_7X7X3_M_2P]  97.15 35 180 bottom
PL300  1UH_11A_20%_7X7X3_M  [L_7X7X3_M_2P]  252.16 26.68 90 bottom
PL500  FBMA-L11-453215800LMA90T_2P  [KC_FBMA-L11-453215800LMA90T_2P]  137.17 142.11 90 bottom
PL501  0.15UH_PCME064T-R15MS0R667_36A_20%  [CYNTE_PCME064T-R15MS0R667_2P]  162.13 135.41 180 bottom
PL502  0.15UH_PCME064T-R15MS0R667_36A_20%  [CYNTE_PCME064T-R15MS0R667_2P]  165.8 135.41 0 bottom
PL503  0.15UH_PCME064T-R15MS0R667_36A_20%  [CYNTE_PCME064T-R15MS0R667_2P]  177.05 131.22 90 bottom
PL505  0.15UH_PCME064T-R15MS0R667_36A_20%  [CYNTE_PCME064T-R15MS0R667_2P]  143.71 134.65 90 bottom
PL506  0.15UH_PCME064T-R15MS0R667_36A_20%  [CYNTE_PCME064T-R15MS0R667_2P]  150.76 134.65 90 bottom
PL508  0.47UH_PCMB053T-R47MS_12A_20%  [CYNTE_PCMB053T-R47MS_2P]  183.24 136.25 270 bottom
PL509  1UH_PCMB042T-1R0MS_4.5A_20%  [CYNTE_PCMB042T-1R0MS_2P]  126.18 111.43 270 bottom
PL700  2.2UH_PCMB104T-2R2MS_12A_20%  [CYNTE_PCMB104T-2R2MS_2P]  65.72 23.91 0 bottom
PL701  1UH_6.6A_20%_5X5X3_M  [L_5X5X3_M_2P]  56.57 29.12 0 bottom
PL800  1UH_PCME051E-1R0MS_6.5A_20%  [CYNTE_PCME051E-1R0MS_2P]  194.89 79.71 90 bottom
PL801  1UH_1239AS-H-1R0M-P2_3A_20%  [TOKO_1239AS-H-1R0M-P2_2P]  230.22 36.94 90 bottom
PL6101  0.22UH_MMD-06DZER22MEM2L__32A_20%  [L_7X7X4_M]  250.8 59.96 90 bottom
PL6102  FBMA-L11-453215800LMA90T_2P  [KC_FBMA-L11-453215800LMA90T_2P]  259.12 31.3 0 bottom
PL6200  0.22UH_MMD-06DZER22MEM2L__32A_20%  [L_7X7X4_M]  242.23 59.96 90 bottom
PL6201  0.22UH_MMD-06DZER22MEM2L__32A_20%  [L_7X7X4_M]  233.66 59.96 90 bottom
PL6300  0.22UH_MMD-06DZER22MEM2L__32A_20%  [L_7X7X4_M]  224.96 60.96 90 bottom
PL6400  0.22UH_MMD-06DZER22MEM2L__32A_20%  [L_7X7X4_M]  272.58 59.52 90 bottom
PL8200  1UH_11A_20%_7X7X3_M  [L_7X7X3_M_2P]  269.16 159.29 180 bottom
PL8201  1UH_11A_20%_7X7X3_M  [L_7X7X3_M_2P]  269.67 167.03 180 bottom
PQ2  S TR METR3904W-G NPN SOT323-3  [RHU002N06_SOT323-3]  272.44 32.77 90 top
PQ3  -  [SI3457CDV-T1-GE3_TSOP6]  68.54 10.89 0 top
PQ4  L2N7002WT1G 1N SC-70-3  [SSM3K7002FU_SC70-3]  70.56 9.24 180 top
PQ7  FDV301N_G 1N SOT23-3  [FDV301N_NL_SOT23-3]  271.52 36.09 270 top
PQ8  L2N7002WT1G 1N SC-70-3  [SSM3K7002FU_SC70-3]  74.24 8.1 270 top
PQ100  -  [AON7518_DFN8-5]  50.68 29.05 0 top
PQ101  -  [AON7534_DFN3X3-8-5]  48.78 31.59 180 top
PQ102  -  [AON7518_DFN8-5]  44.55 37.07 0 top
PQ103  -  [AON7534_DFN3X3-8-5]  47.38 33.56 90 top
PQ200  -  [AON7408L_DFN8-5]  92.05 38.5 180 top
PQ201  -  [AON7506_DFN33-8-5]  93.73 35.4 0 top
PQ202  S TR 2N7002KDW 2N SOT-363-6  [2N7002DW-7-F_SOT363-6]  101.38 54.64 270 top
PQ300  -  [AON7408L_DFN8-5]  253.78 28.14 270 top
PQ301  -  [AON7506_DFN33-8-5]  251.94 21.65 0 top
PQ700  L2N7002WT1G 1N SC-70-3  [SSM3K7002FU_SC70-3]  66.49 32.23 90 top
PQ701  -  [MDU1512RH_POWERDFN56-8-5]  69.74 38.83 270 top
PQ702  -  [MDU1512RH_POWERDFN56-8-5]  67.49 37.98 270 bottom
PQ703  -  [MDU1512RH_POWERDFN56-8-5]  81.59 31.93 270 top
PQ704  -  [AON6414AL_DFN8-5]  69.67 19.59 0 top
PQ705  L2N7002WT1G 1N SC-70-3  [SSM3K7002FU_SC70-3]  63.21 18.76 90 top
PQ706  AON7518 1N DFN  [MDV1525URH_PDFN33-8-5]  65.03 23.59 270 top
PQ707  -  [MDU1512RH_POWERDFN56-8-5]  69.73 34.2 90 bottom
PQ708  -  [MDU1512RH_POWERDFN56-8-5]  67.08 35.1 90 top
PQ710  S TR 2N7002KDW 2N SOT-363-6  [2N7002DW-7-F_SOT363-6]  119.73 78.55 270 top
PQ8200  AON6992 2N DFN5X6D  [FDMS3660S_POWER56-8-7]  271.58 157.07 90 top
PQ8201  AON6992 2N DFN5X6D  [FDMS3660S_POWER56-8-7]  270.43 166.02 90 top
PQ8202  L2N7002WT1G 1N SC-70-3  [SSM3K7002FU_SC70-3]  281.12 153.66 180 top
PR2  1K_0402_1%  [R_0402]  283.74 34.89 90 bottom
PR3  2.2K_0402_5%  [R_0402]  275.37 35.7 270 top
PR4  33_0402_5%  [R_0402]  275.37 37.55 270 top
PR6  100K_0402_1%  [R_0402]  269.73 34.82 90 top
PR8  10K_0402_1%  [R_0402]  273.73 32.54 90 top
PR9  15K_0402_1%  [R_0402]  269.73 33.05 90 top
PR12  100K_0402_1%  [R_0402]  73.94 10.64 180 top
PR13  100K_0402_1%  [R_0402]  71.7 11 90 top
PR14  100K_0402_1%  [R_0402]  67.95 8.17 270 top
PR16  10K_0402_1%  [R_0402]  81.87 8.91 180 top
PR17  0_0402_5%  [R0402_0OHM]  68.86 9.05 180 top
PR19  100_0402_1%  [R_0402]  82.48 11.82 90 top
PR21  100_0402_1%  [R_0402]  81.59 11.82 90 top
PR22  100_0402_1%  [R_0402]  79.79 10.83 270 top
PR23  110K_0402_1%  [R_0402]  292.26 5.4 90 top
PR24  14.7K_0402_1%  [R_0402]  276.36 31.86 90 top
PR25  12.1K_0402_1%  [R_0402]  275.28 31.86 90 top
PR26  100K_0402_1%  [R_0402]  294.14 6.32 270 top
PR28  100K_0402_1%  [R_0402]  77.37 8.73 270 top
PR100  0_0402_5%  [R0402_0OHM]  59.65 48.19 270 top
PR101  6.49K_0402_1%  [R_0402]  57.12 49.47 180 bottom
PR102  15K_0402_1%  [R_0402]  50.88 49.42 180 bottom
PR103  10K_0402_1%  [R_0402]  55.19 49.45 270 bottom
PR104  10K_0402_1%  [R_0402]  52.02 48.53 90 bottom
PR105  113K_0402_1%  [R_0402]  57.11 48.6 180 bottom
PR106  84.5K_0402_1%  [R_0402]  49.97 48.53 0 bottom
PR107  200_0402_1%  [R_0402]  50.12 46.5 180 bottom
PR108  0_0603_5%  [R_0603]  58.62 44.61 180 bottom
PR109  0_0603_5%  [R_0603]  50.74 44.53 180 bottom
PR110  4.7_1206_5%  [R_1206]  44.49 26.93 90 top
PR111  4.7_1206_5%  [R_1206]  42.62 35.04 270 top
PR112  0_0402_5%  [R0402_0OHM]  60.57 48.19 270 top
PR113  2.2K_0402_5%  [R_0402]  61.91 44.35 90 top
PR114  0_0402_5%  [R0402_0OHM]  58.77 48.19 270 top
PR115  1M_0402_1%  [R_0402]  62.79 44.35 90 top
PR116  200K_0402_1%  [R_0402]  62.15 46.14 0 top
PR200  2.2_0603_5%  [R_0603]  88.21 43.78 0 bottom
PR201  24.3K_0402_1%  [R_0402]  97.35 40.8 270 bottom
PR202  4.7_1206_5%  [R_1206]  97.61 38.26 270 top
PR203  5.1_0603_5%  [R_0603]  96.21 39.4 90 bottom
PR204  2.2_0603_5%  [R_0603]  92.27 39.4 90 bottom
PR205  12K_0402_1%  [R_0402]  95.02 48.04 180 bottom
PR206  887K_0402_1%  [R_0402]  96.71 42.69 180 bottom
PR207  20K_0402_1%  [R_0402]  95.02 47.15 180 bottom
PR208  0_0402_5%  [R0402_0OHM]  95.88 43.59 0 bottom
PR209  0_0402_5%  [R_0402]  96.8 46.39 180 bottom
PR210  100K_0402_1%  [R_0402]  96.71 41.79 180 bottom
PR211  0_0402_5%  [R0402_0OHM]  95.88 47.34 0 bottom
PR212  1K_0402_1%  [R_0402]  102.47 51.35 90 top
PR213  60.4K_0402_1%  [R_0402]  101.57 51.33 90 top
PR214  1K_0402_1%  [R_0402]  105.13 55.37 270 top
PR215  60.4K_0402_1%  [R_0402]  104.25 51.35 90 top
PR300  0_0402_5%  [R0402_0OHM]  249.06 17.16 90 top
PR301  100K_0402_1%  [R_0402]  246.13 17.16 90 top
PR302  2.2_0603_5%  [R_0603]  245.34 22.44 90 top
PR303  200K_0402_1%  [R_0402]  247.15 17.16 90 top
PR305  4.7_1206_5%  [R_1206]  252.04 23.66 0 bottom
PR306  470K_0402_1%  [R_0402]  251.85 18.08 270 top
PR307  4.42K_0402_1%  [R_0402]  250.9 18.08 270 top
PR308  10K_0402_1%  [R_0402]  249.94 18.08 270 top
PR500  97.6K_0402_1%  [R_0402]  124.26 137.59 180 top
PR501  45.3_0402_1%  [R_0402]  124.94 132.87 90 top
PR502  75_0402_1%  [R_0402]  125.83 132.87 90 top
PR503  100_0402_1%  [R_0402]  126.72 132.87 90 top
PR504  0_0402_5%  [R0402_0OHM]  124.06 136.2 270 bottom
PR505  1_0402_5%  [R_0402]  126.73 135.29 90 top
PR506  0_0402_5%  [R0402_0OHM]  127.64 136.19 270 top
PR507  0_0402_5%  [R0402_0OHM]  124.95 133.79 270 bottom
PR508  49.9_0402_1%  [R_0402]  124.95 135.29 90 bottom
PR509  0_0402_5%  [R0402_0OHM]  125.84 133.79 270 bottom
PR510  0_0402_5%  [R0402_0OHM]  125.84 135.29 90 bottom
PR511  0_0402_5%  [R0402_0OHM]  126.73 133.79 270 bottom
PR512  10_0402_1%  [R_0402]  126.73 135.29 90 bottom
PR513  27.4K_0402_1%  [R_0402]  119.54 135.24 0 bottom
PR514  12.4K_0402_1%  [R_0402]  120.43 136.13 0 bottom
PR515  1.91K_0402_1%  [R_0402]  123.17 135.29 90 top
PR516  16.9K_0402_1%  [R_0402]  129.39 136.2 270 bottom
PR517  28K_0402_1%  [R_0402]  128.5 136.2 270 bottom
PR518  110K_0402_1%  [R_0402]  127.62 136.2 270 bottom
PR519  169K_0402_1%  [R_0402]  130.28 136.2 270 bottom
PR520  0_0402_5%  [R0402_0OHM]  124.06 135.29 90 top
PR521  3.6K_0402_1%  [R_0402]  123.01 140.64 270 top
PR522  2K_0402_1%  [R_0402]  119.55 139.19 270 bottom
PR523  0_0402_5%  [R0402_0OHM]  123.17 136.2 270 bottom
PR524  1.27K_0402_1%  [R_0402]  132.17 139.37 0 bottom
PR525  1K_0402_1%  [R_0402]  120.44 138.27 90 bottom
PR526  0_0402_5%  [R0402_0OHM]  122.28 136.2 270 bottom
PR527  48.7K_0402_1%  [R_0402]  128.72 137.56 90 top
PR528  1K_0402_1%  [R_0402]  133.1 138.48 270 bottom
PR529  11K_0402_1%  [R_0402]  133.09 142.01 180 bottom
PR530  3.6K_0402_1%  [R_0402]  186.21 134.09 0 bottom
PR531  2.94K_0402_1%  [R_0402]  121.33 139.19 270 bottom
PR532  316_0402_1%  [R_0402]  132.17 143.85 0 bottom
PR533  2.49K_0402_1%  [R_0402]  132.17 142.92 0 bottom
PR534  2.61K_0402_1%  [R_0402]  125.48 147.81 180 top
PR535  11K_0402_1%  [R_0402]  121.34 140.07 180 bottom
PR536  2K_0402_1%  [R_0402]  132.17 144.76 0 bottom
PR537  4.53K_0402_1%  [R_0402]  129.42 141.9 270 top
PR538  1K_0402_1%  [R_0402]  119.5 143.86 0 bottom
PR539  110K_0402_1%  [R_0402]  129.37 143.74 180 top
PR540  294_0402_1%  [R_0402]  119.5 142.97 0 bottom
PR541  383_0402_1%  [R_0402]  127.29 146.03 0 bottom
PR542  11K_0402_1%  [R_0402]  124.38 146.94 270 top
PR543  1K_0402_1%  [R_0402]  129.08 146.94 270 bottom
PR544  4.42K_0402_1%  [R_0402]  123.49 146.94 270 top
PR545  12.4K_0402_1%  [R_0402]  123.41 146.03 0 bottom
PR546  1K_0402_1%  [R_0402]  125.27 146.02 90 bottom
PR547  27.4K_0402_1%  [R_0402]  122.54 146.94 270 bottom
PR548  105K_0402_1%  [R_0402]  123.04 143.51 270 top
PR549  2K_0402_1%  [R_0402]  124.38 146.91 90 bottom
PR550  3.57K_0402_1%  [R_0402]  126.15 146.94 270 bottom
PR551  4.87K_0402_1%  [R_0402]  124.91 144.43 0 top
PR552  0_0402_5%  [R0402_0OHM]  157.4 146.45 90 bottom
PR553  1_0402_5%  [R_0402]  159.18 146.45 90 bottom
PR554  4.7_0603_1%  [R_0603]  161.68 147.72 270 bottom
PR555  10_1206_5%  [R_1206]  157.67 137.9 0 top
PR556  0_0402_5%  [R0402_0OHM]  158.29 146.45 90 bottom
PR557  3.65K_0603_1%  [R_0603]  158.73 136.26 0 top
PR558  100K_0402_1%  [R_0402]  159.58 135.05 180 top
PR559  10_0402_1%  [R_0402]  159.61 133.25 90 top
PR560  100K_0402_1%  [R_0402]  158.69 133.24 90 top
PR561  100K_0402_1%  [R_0402]  157.77 133.25 90 top
PR562  20M_0402_5%  [R_0402]  157.74 136.45 270 top
PR563  0_0402_5%  [R0402_0OHM]  165.93 146.36 90 bottom
PR564  4.7_0603_1%  [R_0603]  170.01 147.64 270 bottom
PR565  10_1206_5%  [R_1206]  167.2 137.83 0 top
PR566  0_0402_5%  [R0402_0OHM]  166.82 146.36 90 bottom
PR567  3.65K_0603_1%  [R_0603]  167.07 136.24 0 top
PR568  100K_0402_1%  [R_0402]  168 135.18 180 top
PR569  10_0402_1%  [R_0402]  168.03 133.37 90 top
PR570  100K_0402_1%  [R_0402]  166.18 133.37 90 top
PR571  100K_0402_1%  [R_0402]  167.07 133.37 90 top
PR572  20M_0402_5%  [R_0402]  141.42 140.19 270 top
PR573  0_0402_5%  [R0402_0OHM]  174.27 146.37 90 bottom
PR574  4.7_0603_1%  [R_0603]  178.35 147.69 270 bottom
PR575  10_1206_5%  [R_1206]  175.46 137.89 0 top
PR576  0_0402_5%  [R0402_0OHM]  175.16 146.38 90 bottom
PR577  3.65K_0603_1%  [R_0603]  175.27 136.23 0 top
PR578  100K_0402_1%  [R_0402]  176.1 135.1 180 top
PR579  10_0402_1%  [R_0402]  176.09 133.25 90 top
PR580  100K_0402_1%  [R_0402]  175.14 133.25 90 top
PR581  100K_0402_1%  [R_0402]  174.25 133.25 90 top
PR582  20M_0402_5%  [R_0402]  187.2 131.85 90 top
PR583  4.7_0603_1%  [R_0603]  145.66 150.96 270 bottom
PR584  4.7_1206_5%  [R_1206]  142.56 141.07 0 top
PR585  0_0402_5%  [R0402_0OHM]  142.47 149.65 90 bottom
PR586  3.65K_0603_1%  [R_0603]  142.47 139.44 0 top
PR587  100K_0402_1%  [R_0402]  143.31 138.38 180 top
PR588  10_0402_1%  [R_0402]  143.32 136.59 90 top
PR589  100K_0402_1%  [R_0402]  142.34 136.58 90 top
PR590  0_0402_5%  [R0402_0OHM]  141.58 149.65 90 bottom
PR591  0_0402_5%  [R0402_0OHM]  149.91 149.67 90 bottom
PR592  4.7_0603_1%  [R_0603]  154 150.98 270 bottom
PR593  4.7_1206_5%  [R_1206]  151.2 141.07 0 top
PR594  0_0402_5%  [R0402_0OHM]  150.8 149.67 90 bottom
PR595  3.65K_0603_1%  [R_0603]  150.58 139.4 0 top
PR596  100K_0402_1%  [R_0402]  151.4 138.34 180 top
PR597  10_0402_1%  [R_0402]  151.42 136.58 90 top
PR598  100K_0402_1%  [R_0402]  150.47 136.58 90 top
PR599  10K_0402_1%  [R_0402]  157.34 144.15 270 top
PR700  1M_0402_1%  [R_0402]  62.41 30.76 90 top
PR701  3M_0402_5%  [R_0402]  63.36 31.66 270 top
PR702  0.005_2512_1%  [R_2512_4P]  58.75 42.32 180 bottom
PR703  0_0402_5%  [R0402_0OHM]  59.5 26.78 270 top
PR704  0_0402_5%  [R0402_0OHM]  60.39 26.78 270 top
PR705  4.12K_0603_1%  [R_0603]  57.07 27.6 270 top
PR706  4.12K_0603_1%  [R_0603]  58.29 27.6 270 top
PR707  10_1206_1%  [R_1206]  61.96 18.7 90 bottom
PR708  2.2_0603_5%  [R_0603]  62.81 21.69 180 top
PR709  20K_0402_1%  [R_0402]  59.25 18.59 270 top
PR710  5.11K_0402_1%  [R_0402]  63.64 16.91 90 top
PR711  3.16K_0402_1%  [R_0402]  60.14 18.59 270 top
PR712  0.01_1206_1%  [R_1206_4P-D]  79.83 26.32 270 bottom
PR713  4.7_1206_5%  [R_1206]  67.38 19.59 180 top
PR714  100K_0402_1%  [R_0402]  55.96 27.04 270 top
PR715  120K_0402_5%  [R_0402]  57.24 24.86 270 bottom
PR716  324K_0402_1%  [R_0402]  55.08 27.04 270 top
PR717  0_0402_5%  [R0402_0OHM]  52.97 25.62 0 top
PR718  10K_0402_1%  [R_0402]  56.14 18.65 270 top
PR719  49.9K_0402_1%  [R_0402]  55.32 24.87 270 bottom
PR720  0_0402_5%  [R0402_0OHM]  52.91 22.01 0 top
PR721  0_0402_5%  [R0402_0OHM]  52.92 21.12 0 top
PR722  10_0402_1%  [R_0402]  58.37 18.59 270 top
PR723  10_0402_1%  [R_0402]  57.48 18.59 270 top
PR724  0_0402_5%  [R_0402]  52.91 22.89 0 top
PR725  4.7_0402_5%  [R_0402]  67.26 33.37 0 top
PR726  4.7_0402_5%  [R_0402]  67.37 40.58 0 top
PR727  0_0402_5%  [R0402_0OHM]  55.25 17.74 90 top
PR728  0_0402_5%  [R_0402]  56.27 22.56 180 bottom
PR729  1M_0402_1%  [R_0402]  122.63 78.77 270 top
PR730  1M_0402_1%  [R_0402]  120.79 79.71 0 top
PR731  200K_0402_1%  [R_0402]  117.75 76.92 90 top
PR732  3.3K_0402_1%  [R_0402]  118.63 76.92 90 top
PR733  10K_0402_1%  [R_0402]  79.89 27.4 180 top
PR734  10_0402_1%  [R_0402]  78.9 29.43 270 top
PR801  100K_0402_1%  [R_0402]  196.01 72.83 0 top
PR802  120K_0402_1%  [R_0402]  196.09 73.69 90 top
PR803  4.7_0603_5%  [R_0603]  197.83 78.77 270 top
PR804  12K_0402_1%  [R_0402]  193.05 76.63 0 bottom
PR805  35.7K_0402_1%  [R_0402]  195.3 75.61 0 top
PR806  0_0603_5%  [R_0603]  199.59 78.45 90 bottom
PR807  0_0402_5%  [R0402_0OHM]  231.09 40.23 180 bottom
PR808  1M_0402_1%  [R_0402]  232.1 40.21 90 bottom
PR809  4.7_0603_5%  [R_0603]  229.5 35.66 0 bottom
PR810  20K_0402_1%  [R_0402]  236.91 40.48 0 bottom
PR811  10K_0402_1%  [R_0402]  236.91 39.53 0 bottom
PR812  0_0402_5%  [R_0402]  193.87 75.42 270 bottom
PR813  0_0402_5%  [R_0402]  192.92 74.5 90 bottom
PR1300  100K_0402_1%  [R_0402]  97.52 49.71 270 bottom
PR1301  0_0402_5%  [R0402_0OHM]  98.34 50.71 90 bottom
PR1302  1M_0402_1%  [R_0402]  99.23 50.71 90 bottom
PR1303  510_0402_1%  [R_0402]  202.02 70.45 180 top
PR1304  21.5K_0402_1%  [R_0402]  101.17 42.17 180 bottom
PR1305  10K_0402_1%  [R_0402]  99.35 42.16 180 bottom
PR1307  12.7K_0402_1%  [R_0402]  210.51 76.94 270 bottom
PR1308  1M_0402_1%  [R_0402]  202.02 71.34 180 top
PR1309  10K_0402_1%  [R_0402]  210.51 75.17 270 bottom
PR5001  0_0402_5%  [R0402_0OHM]  180.92 145.84 270 bottom
PR5002  4.7_1206_5%  [R_1206]  185.33 133.33 90 top
PR5003  3.65K_0603_1%  [R_0603]  184.83 132.06 0 top
PR5004  1_0402_5%  [R_0402]  167.7 146.36 90 bottom
PR5005  1_0603_5%  [R_0603]  185.43 146.21 270 bottom
PR5006  0_0402_5%  [R0402_0OHM]  181.81 144.93 90 bottom
PR5007  0_0402_5%  [R0402_0OHM]  124.52 117.32 0 bottom
PR5008  1M_0402_1%  [R_0402]  124.52 119.1 0 bottom
PR5009  4.7_1206_5%  [R_1206]  120.98 110.46 180 bottom
PR5010  0_0603_5%  [R_0603]  118.31 114.84 270 bottom
PR5011  10K_0402_1%  [R_0402]  166.75 142.65 180 top
PR5012  21K_0402_1%  [R_0402]  121.13 121.58 90 bottom
PR5014  10_0402_1%  [R_0402]  122.04 122.5 270 bottom
PR5015  35.7K_0402_1%  [R_0402]  120.25 122.47 270 bottom
PR5016  10K_0402_5%  [R_0402]  123.45 120.69 270 bottom
PR5017  0_0402_5%  [R0402_0OHM]  124.16 121.64 180 bottom
PR5018  0_0402_5%  [R0402_0OHM]  124.16 122.53 180 bottom
PR5019  10K_0402_1%  [R_0402]  174.02 144.19 270 top
PR5020  1_0402_5%  [R_0402]  176.05 146.38 90 bottom
PR5021  10K_0402_1%  [R_0402]  141.33 147.45 270 top
PR5022  1_0402_5%  [R_0402]  143.36 149.65 90 bottom
PR5023  10K_0402_1%  [R_0402]  149.66 147.47 270 top
PR5024  1_0402_5%  [R_0402]  151.69 149.67 90 bottom
PR5025  1_0402_5%  [R_0402]  182.69 144.93 90 bottom
PR5026  1_0402_5%  [R_0402]  181.17 140.75 0 top
PR5027  10_0402_1%  [R_0402]  187.13 132.31 180 bottom
PR5028  1_0402_5%  [R_0402]  158.22 142.36 180 top
PR5029  1_0402_5%  [R_0402]  165.92 141.78 270 top
PR5030  1_0402_5%  [R_0402]  174.87 142.42 180 top
PR5031  1_0402_5%  [R_0402]  142.22 145.66 180 top
PR5032  1_0402_5%  [R_0402]  150.55 145.71 180 top
PR5033  0_0402_5%  [R_0402]  124.52 115.16 0 bottom
PR5034  0_0402_5%  [R0402_0OHM]  125.43 116.43 180 bottom
PR6000  2.2_0603_1%  [R_0603]  298.78 53.44 180 top
PR6001  1K_0402_5%  [R_0402]  289.52 59.6 180 top
PR6002  1K_0402_5%  [R_0402]  287.91 58.64 180 top
PR6003  1K_0603_1%  [R_0603]  293.18 53.02 180 bottom
PR6004  1K_0402_5%  [R_0402]  298.67 60.87 180 top
PR6005  1K_0402_5%  [R_0402]  298.67 59.98 180 top
PR6006  1K_0402_5%  [R_0402]  298.67 59.09 180 top
PR6007  0_0402_5%  [R0402_0OHM]  292.63 59.4 180 bottom
PR6008  0_0402_5%  [R0402_0OHM]  292.63 60.29 180 bottom
PR6009  10K_0402_1%  [R_0402]  282.7 56.48 0 top
PR6010  0_0402_5%  [R0402_0OHM]  292.63 58.52 180 bottom
PR6011  0_0402_5%  [R0402_0OHM]  292.63 57.63 180 bottom
PR6012  100K_0402_5%  [R_0402]  280.55 54.12 90 bottom
PR6013  10_0402_1%  [R_0402]  279.68 55.28 180 bottom
PR6015  3.65K_0402_1%  [R_0402]  278.77 54.13 0 bottom
PR6016  19.6K_0402_1%  [R_0402]  282.7 54.71 0 top
PR6017  120K_0402_1%  [R_0402]  291.72 54.07 0 bottom
PR6018  0_0402_5%  [R0402_0OHM]  298.67 54.64 180 top
PR6019  100K_0402_5%  [R_0402]  281.44 59.77 90 bottom
PR6020  10_0402_1%  [R_0402]  279.68 58.9 180 bottom
PR6021  3.65K_0402_1%  [R_0402]  278.76 59.79 0 bottom
PR6022  3.65K_0402_1%  [R_0402]  278.77 58.01 0 bottom
PR6023  10K_0402_1%  [R_0402]  282.76 53.82 0 top
PR6024  47_0402_5%  [R_0402]  288.24 64.5 270 bottom
PR6025  2.2K_0402_1%  [R_0402]  289.96 62.71 180 bottom
PR6026  10_0402_1%  [R_0402]  281.69 62.48 180 bottom
PR6027  100K_0402_5%  [R_0402]  281.68 64.36 180 bottom
PR6028  1K_0402_0.5%  [R_0402]  289.11 64.48 0 bottom
PR6029  3.65K_0402_1%  [R_0402]  283.49 64.37 270 bottom
PR6031  562K_0402_1%  [R_0402]  288.87 61.51 270 top
PR6033  10_0402_1%  [R_0402]  279.66 60.67 180 bottom
PR6037  100_0402_5%  [R_0402]  240.47 75.97 90 bottom
PR6039  0_0402_5%  [R0402_0OHM]  290.9 62.66 270 bottom
PR6040  80.6K_0603_1%  [R_0603]  284.55 68.03 90 bottom
PR6041  0_0402_5%  [R0402_0OHM]  293.96 62.64 180 bottom
PR6042  47K_0402_1%  [R_0402]  285.31 63.58 90 bottom
PR6043  100K_0402_5%  [R_0402]  284.36 64.5 270 bottom
PR6044  80.6K_0603_1%  [R_0603]  282.39 68.04 90 bottom
PR6045  100_0402_5%  [R_0402]  239.52 76.88 270 bottom
PR6046  80.6K_0603_1%  [R_0603]  281.14 67.85 180 bottom
PR6047  45.3K_0402_1%  [R_0402]  287.16 61.74 90 bottom
PR6048  80.6K_0603_1%  [R_0603]  281.14 65.75 180 bottom
PR6049  26.1K_0402_1%  [R_0402]  287.47 60.43 270 top
PR6050  1K_0402_0.5%  [R_0402]  287.17 63.6 180 bottom
PR6052  3.32K_0402_1%  [R_0402]  286.2 62.66 270 bottom
PR6054  10_0402_1%  [R_0402]  285.63 69.01 270 bottom
PR6055  10_0402_1%  [R_0402]  283.47 68.94 270 bottom
PR6056  0_0402_5%  [R0402_0OHM]  292.63 54.96 180 bottom
PR6057  10_0402_1%  [R_0402]  280.22 68.93 0 bottom
PR6058  10_0402_1%  [R_0402]  280.22 66.8 0 bottom
PR6059  47_0402_5%  [R_0402]  288.35 51.02 0 bottom
PR6060  2.2K_0402_1%  [R_0402]  290.13 50.13 0 bottom
PR6061  10K_0402_1%  [R_0402]  282.14 52.37 270 bottom
PR6063  1K_0402_0.5%  [R_0402]  288.35 51.91 0 bottom
PR6064  10_0402_1%  [R_0402]  283.54 51.45 90 top
PR6065  562K_0402_1%  [R_0402]  290.13 51.91 0 bottom
PR6066  3.65K_0402_1%  [R_0402]  283.23 49.69 180 bottom
PR6067  100_0402_5%  [R_0402]  235.35 91.47 0 top
PR6068  120K_0603_1%  [R_0603]  282.14 48.61 0 bottom
PR6069  47K_0402_1%  [R_0402]  284.62 49.38 270 bottom
PR6070  100K_0402_5%  [R_0402]  285.56 47.59 0 bottom
PR6071  0_0402_5%  [R0402_0OHM]  288.31 52.1 180 top
PR6072  3.48K_0402_1%  [R_0402]  286.34 52.1 180 top
PR6073  26.1K_0402_1%  [R_0402]  285.77 53.35 90 top
PR6074  4.7K_0402_5%  [R_0402]  297.76 58.2 0 top
PR6075  4.7K_0402_5%  [R_0402]  297.76 57.31 0 top
PR6077  1K_0402_0.5%  [R_0402]  285.57 50.31 90 bottom
PR6078  3.32K_0402_1%  [R_0402]  285.56 52.1 0 bottom
PR6079  0_0402_5%  [R_0402]  292.63 56.74 180 bottom
PR6080  0_0402_5%  [R_0402]  292.63 55.85 180 bottom
PR6081  0_0402_5%  [R0402_0OHM]  289.19 51.26 90 top
PR6082  60.4K_0402_1%  [R_0402]  286.99 54.41 0 top
PR6083  100K_0402_5%  [R_0402]  280.54 58.02 90 bottom
PR6084  169K_0402_1%  [R_0402]  283.07 55.58 0 top
PR6085  2K_0402_1%  [R_0402]  280.78 61.59 0 bottom
PR6086  0_0402_5%  [R_0402]  282.57 63.46 90 bottom
PR6087  0_0402_5%  [R_0402]  298.67 56.42 180 top
PR6088  0_0402_5%  [R0402_0OHM]  298.67 55.54 180 top
PR6089  0_0402_5%  [R_0402]  297.76 61.77 0 top
PR6090  0_0402_5%  [R0402_0OHM]  297.76 62.66 0 top
PR6112  2.2_0603_1%  [R_0603]  247.62 55.42 90 top
PR6113  3.9_0603_1%  [R_0603]  248.48 51.46 270 bottom
PR6114  2.2_0805_5%  [R_0805]  253.28 58.5 270 top
PR6209  2.2_0603_1%  [R_0603]  239.05 55.42 90 top
PR6210  3.9_0603_1%  [R_0603]  239.91 51.47 270 bottom
PR6211  2.2_0805_5%  [R_0805]  244.73 58.4 270 top
PR6212  2.2_0603_1%  [R_0603]  230.48 55.42 90 top
PR6213  3.9_0603_1%  [R_0603]  231.34 51.47 270 bottom
PR6214  2.2_0805_5%  [R_0805]  236.17 58.4 270 top
PR6309  2.2_0603_1%  [R_0603]  221.78 56.42 90 top
PR6310  3.9_0603_1%  [R_0603]  222.65 52.46 270 bottom
PR6311  2.2_0805_5%  [R_0805]  227.48 59.41 270 top
PR6400  2.2_0603_1%  [R_0603]  266 54.91 90 bottom
PR6401  3.9_0603_1%  [R_0603]  268.09 50.3 270 bottom
PR6402  2.2_0805_5%  [R_0805]  275.98 56.32 270 bottom
PR8200  2.2_0603_5%  [R_0603]  272.85 155.97 225 bottom
PR8201  2.2_0402_1%  [R_0402]  282 161.56 180 top
PR8202  383K_0402_1%  [R_0402]  281.09 159.81 0 top
